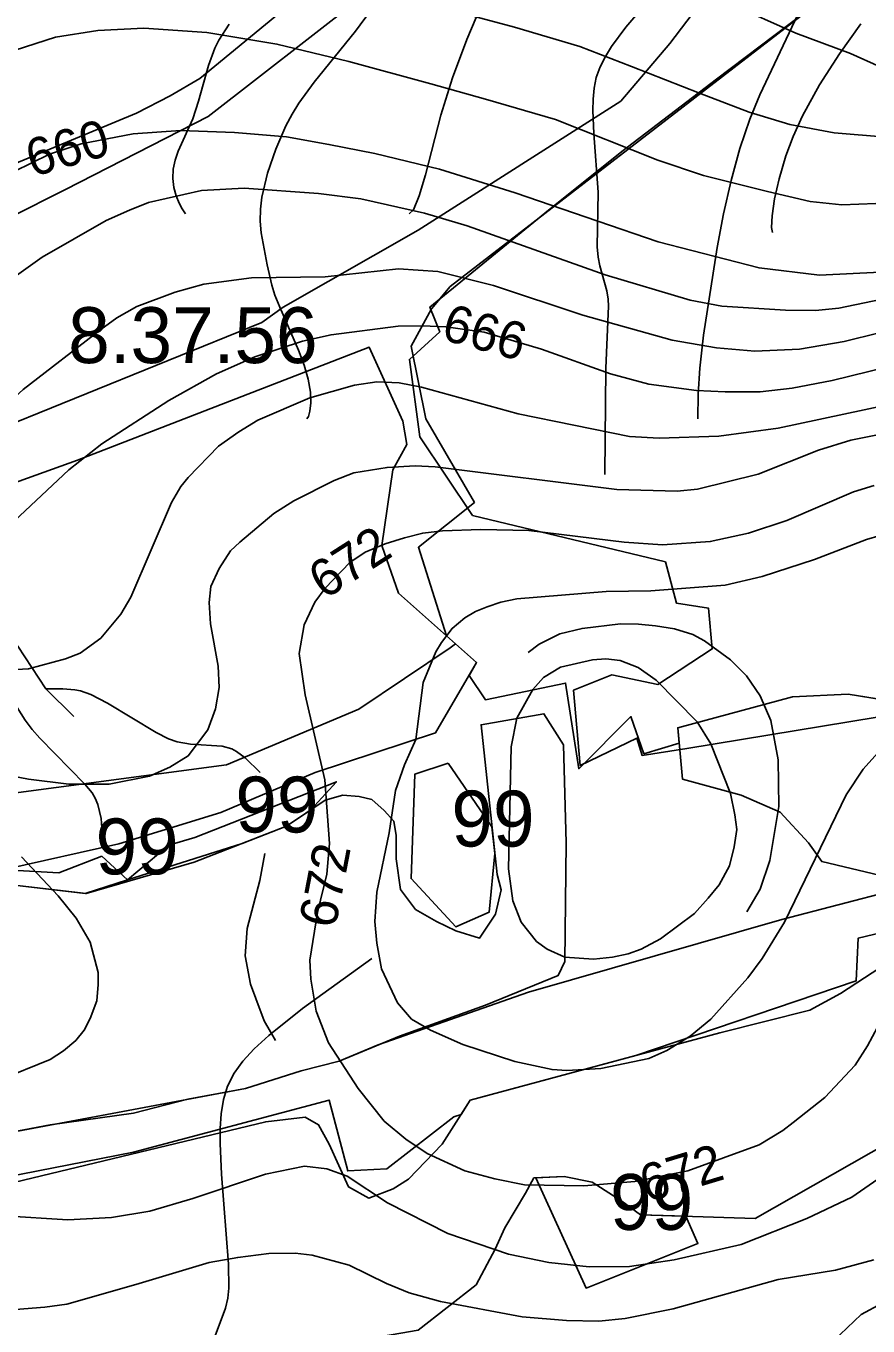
# Model space of a CAD drawing. Extents: x -709584 to -702006, y -1161789 to -1157496.
# Drawn here: x -706462.3 to -706236.4, y -1160518.2 to -1160169 of the extents above; entities that cross this region are included whole.
import ezdxf

# ---------------------------------------------------------------- set-up
doc = ezdxf.new("R2010")
doc.units = 0
for name, color, linetype in [('102_obvod PÚ', 7, 'Continuous'), ('120_vrstevnice hlavní', 7, 'Continuous'), ('121_vrstevnice hlavní_popis', 7, 'Continuous'), ('122_vrstevnice základní', 7, 'Continuous'), ('124_vrstevnice doplňková', 7, 'Continuous'), ('408_BPEJ_linie', 7, 'Continuous'), ('409_BPEJ_popis', 7, 'Continuous'), ('411_akumulovaný odtok', 7, 'Continuous'), ('419_LPIS PB', 7, 'Continuous')]:
    doc.layers.add(name, color=color, linetype=linetype)

msp = doc.modelspace()

# ---------------------------------------------------------------- linework, layer by layer
at = {"layer": '102_obvod PÚ'}
for points in [[(-706359.43, -1160258.57), (-706351.29, -1160251.18), (-706353.92, -1160244.52), (-706323.05, -1160219.34), (-706302.42, -1160202.71), (-706277.05, -1160183.32), (-706245.92, -1160159.66)], [(-706245.92, -1160159.66), (-706277.05, -1160183.32), (-706302.42, -1160202.71), (-706323.05, -1160219.34), (-706353.92, -1160244.52), (-706351.29, -1160251.18), (-706359.43, -1160258.57), (-706356.6, -1160279.34), (-706342.48, -1160300.47), (-706290.74, -1160312.96), (-706287.73, -1160324.07), (-706279.13, -1160325.42), (-706278.18, -1160336.32), (-706292.79, -1160345.84), (-706305.11, -1160343.25), (-706315.41, -1160347.43), (-706313.62, -1160367.6), (-706298.39, -1160360.29), (-706297.01, -1160364.93), (-706285.01, -1160363.05), (-706219.24, -1160352.25)], [(-706219.24, -1160352.25), (-706285.01, -1160363.05), (-706297.01, -1160364.93), (-706298.39, -1160360.29), (-706313.62, -1160367.6), (-706315.41, -1160347.43), (-706305.11, -1160343.25), (-706292.79, -1160345.84), (-706278.18, -1160336.32), (-706279.13, -1160325.42), (-706287.73, -1160324.07), (-706290.74, -1160312.96), (-706342.48, -1160300.47), (-706356.6, -1160279.34), (-706359.43, -1160258.57)]]:
    msp.add_lwpolyline(points, dxfattribs=at)
at = {"layer": '120_vrstevnice hlavní'}
for points in [[(-706406.41, -1160197.67), (-706420.89, -1160197.05), (-706433.54, -1160198.03), (-706447.53, -1160200.69), (-706456.05, -1160203.43), (-706465.53, -1160208.15), (-706473.52, -1160213.84), (-706491, -1160227.07), (-706512.32, -1160245.59)], [(-706233.09, -1160235.12), (-706249.34, -1160235.97), (-706265.58, -1160233.98), (-706292.65, -1160226.99), (-706308.9, -1160221.44), (-706331.07, -1160213.8), (-706351.38, -1160207.47), (-706368.68, -1160203.29), (-706381.04, -1160200.81), (-706392.42, -1160198.81), (-706406.41, -1160197.67)], [(-706233.38, -1160278.72), (-706240.95, -1160280.28), (-706249.62, -1160282.99), (-706265.87, -1160289.41), (-706282.11, -1160293.4), (-706287.53, -1160293.97), (-706303.77, -1160293.54), (-706352.5, -1160287.41), (-706357.92, -1160287.13), (-706365.44, -1160287.56), (-706374.36, -1160289.06), (-706379.58, -1160291.12), (-706390.41, -1160296.53), (-706395.82, -1160299.95), (-706404.94, -1160307.65), (-706407.45, -1160310), (-706410.5, -1160314.77), (-706412.75, -1160319.53), (-706413.2, -1160323.89), (-706412.78, -1160329.59), (-706410.78, -1160340.99), (-706410.5, -1160346.69), (-706411.5, -1160352.39), (-706413.49, -1160358.09), (-706418.76, -1160365.07), (-706423.75, -1160368.06), (-706429.16, -1160370.49), (-706439.99, -1160372.62), (-706450.82, -1160372.62), (-706461.65, -1160371.34), (-706488.73, -1160366.07)], [(-706468.21, -1160488.61), (-706451.11, -1160489.61), (-706439.42, -1160489.07), (-706429.08, -1160487.31), (-706417.57, -1160483.93), (-706398.06, -1160477.41), (-706387.56, -1160475.22), (-706381.57, -1160475.93), (-706376.16, -1160477.93), (-706365.33, -1160485.05), (-706349.08, -1160493.31), (-706332.84, -1160498.87), (-706322.01, -1160501.15), (-706311.18, -1160502.29), (-706300.35, -1160502.15), (-706288.38, -1160500.44), (-706270.43, -1160496.31), (-706252.76, -1160489.32), (-706240.72, -1160483.55), (-706232.52, -1160477.93)]]:
    msp.add_lwpolyline(points, dxfattribs=at)
at = {"layer": '122_vrstevnice základní'}
for points in [[(-706368.04, -1160159.39), (-706331.2, -1160169.31), (-706313.68, -1160174.53), (-706299.81, -1160179.91), (-706281.61, -1160187.09), (-706268.21, -1160192.2), (-706257.3, -1160195.52), (-706245.42, -1160197.68), (-706231.38, -1160198.92), (-706207.73, -1160200.35), (-706180.37, -1160203.34), (-706173.8, -1160204.42), (-706166.69, -1160206.48), (-706160.48, -1160208.44), (-706153.01, -1160211.61), (-706147.31, -1160214.96), (-706141.61, -1160219.16), (-706112.68, -1160245.09), (-706085.18, -1160267.6), (-706069.22, -1160278.01), (-706048.7, -1160288.55), (-706037.31, -1160295.82), (-706023.91, -1160306.79)], [(-706273.31, -1160163.12), (-706255.75, -1160170.97), (-706241.07, -1160176.41), (-706233.09, -1160179.97), (-706223.12, -1160183.53), (-706201.17, -1160188.52), (-706187.21, -1160190.37), (-706173.24, -1160192.94), (-706161.28, -1160197.07), (-706149.31, -1160202.2), (-706139.33, -1160207.47), (-706125.22, -1160217.59), (-706114.25, -1160227.28), (-706091.31, -1160251.07), (-706082.33, -1160258.06), (-706072.36, -1160264.33), (-706060.53, -1160270.31), (-706052.12, -1160273.87), (-706033.99, -1160279.91), (-705988.29, -1160297.96)], [(-706375.67, -1160178.57), (-706394.98, -1160173.87), (-706413.78, -1160170.81), (-706430.72, -1160169.63), (-706443.05, -1160170.28), (-706454.38, -1160172.06), (-706465.2, -1160175.48), (-706475.34, -1160180.88), (-706483.65, -1160187.72), (-706491.11, -1160195.88), (-706502.82, -1160210.9), (-706514.66, -1160223.29), (-706532.55, -1160239.97), (-706558.13, -1160260.92)], [(-706220.55, -1160216.16), (-706243.35, -1160217.02), (-706251.9, -1160216.16), (-706263.3, -1160213.46), (-706280.53, -1160209.15), (-706292.76, -1160205.03), (-706320.21, -1160194.17), (-706339.04, -1160188.65), (-706353.71, -1160184.55), (-706375.67, -1160178.57)], [(-706221.41, -1160240.1), (-706244.21, -1160244.8), (-706250.46, -1160245.42), (-706258.46, -1160245.38), (-706275.56, -1160244.24), (-706284.1, -1160242.67), (-706306.9, -1160235.83), (-706343.95, -1160222.72), (-706355.35, -1160219.3), (-706372.45, -1160215.45), (-706383.85, -1160214.03), (-706403.8, -1160212.6), (-706415.2, -1160213.17), (-706429.45, -1160216.45), (-706434.55, -1160218.47), (-706440.85, -1160221.29), (-706457.95, -1160231.13), (-706472.2, -1160241.24)], [(-706223.97, -1160249.08), (-706242.78, -1160253.78), (-706254.75, -1160255.78), (-706266.72, -1160256.35), (-706276.98, -1160255.49), (-706288.95, -1160253.36), (-706312.89, -1160246.66), (-706336.83, -1160238.68), (-706351.79, -1160234.97), (-706362.33, -1160234.24), (-706382.05, -1160236.4)], [(-706382.05, -1160236.4), (-706401.81, -1160236.68), (-706414.63, -1160238.39), (-706422.32, -1160240.53), (-706432.58, -1160244.38), (-706437.92, -1160247.43), (-706442.27, -1160250.51), (-706463.08, -1160266.61), (-706476.9, -1160279.29), (-706488.87, -1160287.98)], [(-706466.92, -1160303.37), (-706450.82, -1160288.27), (-706441.99, -1160281.28), (-706424.03, -1160269.6), (-706411.21, -1160262.48), (-706400.95, -1160257.92), (-706388.13, -1160253.64), (-706380.43, -1160251.93), (-706362.48, -1160249.65), (-706355.95, -1160249.56), (-706349.65, -1160249.79), (-706339.39, -1160251.22), (-706324, -1160255.78), (-706305.48, -1160262.48), (-706295.22, -1160265.18), (-706282.4, -1160266.89), (-706274.7, -1160267.32), (-706265.26, -1160267.25), (-706256.75, -1160266.32), (-706245.94, -1160264.23), (-706220.84, -1160258.06)], [(-706219.76, -1160268.37), (-706260.45, -1160277.01), (-706276.41, -1160279.15), (-706292.37, -1160279.72), (-706300.35, -1160279.29), (-706330.27, -1160273.16), (-706356.21, -1160266.04), (-706362.19, -1160264.9), (-706368.18, -1160264.61), (-706374.16, -1160265.47), (-706386.13, -1160268.89), (-706400.09, -1160274.87), (-706405.25, -1160278.03), (-706410.66, -1160281.85)], [(-706410.66, -1160281.85), (-706418.76, -1160290.26), (-706420.77, -1160292.7), (-706423.32, -1160296.96), (-706434.15, -1160322.47), (-706436.86, -1160327.03), (-706442.27, -1160333.44), (-706447.83, -1160337.43), (-706451.68, -1160338.99), (-706461.65, -1160341.7), (-706505.54, -1160344.12)], [(-706234.74, -1160292.45), (-706240.22, -1160294.11), (-706258.17, -1160301.8), (-706268.43, -1160305.22), (-706278.69, -1160307.5), (-706291.51, -1160308.36), (-706301.77, -1160307.65), (-706327.42, -1160304.51), (-706340.25, -1160304.23), (-706350.51, -1160304.65), (-706355.87, -1160305.23), (-706360.77, -1160306.51), (-706365.9, -1160308.07)], [(-706365.9, -1160308.07), (-706371.26, -1160310.38), (-706375.44, -1160313.09), (-706382, -1160320.04), (-706384.83, -1160323.79), (-706387.7, -1160329.88), (-706388.98, -1160337.57), (-706387.41, -1160348.68), (-706382.14, -1160371.48), (-706380.86, -1160388.58), (-706381.57, -1160396.85), (-706384.14, -1160407.11), (-706386.13, -1160419.93), (-706385.85, -1160425.06), (-706384.42, -1160433.61), (-706381.14, -1160442.16), (-706373.16, -1160454.42), (-706366.18, -1160463.11), (-706360.43, -1160468), (-706354.64, -1160471.8), (-706344.52, -1160476.5), (-706336.51, -1160478.66), (-706328.56, -1160480.21), (-706312.6, -1160480.49), (-706298.92, -1160479.35), (-706284.68, -1160476.5), (-706265.58, -1160469.52), (-706259.21, -1160465.62), (-706256.46, -1160463.53), (-706247.91, -1160456.84), (-706239.79, -1160448.15), (-706236.47, -1160442.92), (-706233.8, -1160437.89)], [(-706233.06, -1160305.86), (-706236.8, -1160306.93), (-706250.76, -1160312.35), (-706264.73, -1160316.91), (-706274.7, -1160319.19), (-706294.65, -1160320.76), (-706306.62, -1160320.9), (-706330.56, -1160322.89), (-706334.94, -1160323.79), (-706338.54, -1160325.03), (-706341.65, -1160326.3), (-706344.52, -1160328.02), (-706347.98, -1160330.81), (-706350.79, -1160334.58)], [(-706350.79, -1160334.58), (-706352.36, -1160337.14), (-706355.71, -1160345.33), (-706357.67, -1160360.66), (-706360.78, -1160367.43), (-706363.19, -1160374.33), (-706364.9, -1160385.73), (-706368.18, -1160401.69), (-706368.72, -1160409.57), (-706368.18, -1160415.37), (-706366.89, -1160422.21), (-706362.62, -1160431.33), (-706358.91, -1160435.75), (-706353.78, -1160438.74), (-706345.09, -1160442.59), (-706331.13, -1160447.15), (-706321.15, -1160449.28), (-706317.16, -1160449.57), (-706308.04, -1160449), (-706295.22, -1160446.29), (-706290.37, -1160444.16), (-706284.1, -1160440.31), (-706278.55, -1160435.75), (-706268.57, -1160424.63), (-706264.73, -1160419.5), (-706258.74, -1160409.67), (-706242.21, -1160375.47), (-706237.65, -1160368.63), (-706231.38, -1160361.65)], [(-706298.08, -1160341.35), (-706293.22, -1160344.69), (-706282.24, -1160355.89), (-706278.55, -1160361.79), (-706273.28, -1160375.19), (-706272.14, -1160380.89), (-706271.58, -1160384.86), (-706272.28, -1160389.44), (-706273.56, -1160394.57), (-706276.27, -1160399.7), (-706279.27, -1160403.3), (-706282.96, -1160407.39), (-706292.08, -1160414.23), (-706297.21, -1160416.94), (-706300.72, -1160418.22), (-706304.91, -1160419.08), (-706310.04, -1160419.65), (-706317.73, -1160419.08), (-706322.44, -1160416.94), (-706325.29, -1160414.94), (-706329.42, -1160409.67), (-706331.7, -1160403.97), (-706332.84, -1160395.42), (-706332.12, -1160362.65), (-706330.56, -1160354.95), (-706326.28, -1160347.26), (-706323.42, -1160343.99), (-706318.87, -1160341.27), (-706310.32, -1160339.28), (-706306.74, -1160338.97), (-706302.91, -1160339.42), (-706298.08, -1160341.35)], [(-706471.91, -1160514.26), (-706457.25, -1160513.14), (-706451.39, -1160512.27), (-706432.87, -1160507), (-706413.21, -1160501.15), (-706405.51, -1160499.73), (-706397.15, -1160498.72), (-706390.12, -1160498.59), (-706385.56, -1160499.16), (-706375.59, -1160501.86), (-706365.61, -1160506.71), (-706359.53, -1160509.25), (-706351.08, -1160511.55), (-706329.13, -1160515.69), (-706317.31, -1160516.66)], [(-706317.31, -1160516.66), (-706308.61, -1160516.83), (-706301.49, -1160516.11), (-706288.67, -1160513.55), (-706260.45, -1160505.71), (-706245.06, -1160503.15), (-706234.8, -1160500.44)]]:
    msp.add_lwpolyline(points, dxfattribs=at)
at = {"layer": '124_vrstevnice doplňková'}
for points in [[(-706268.86, -1160406.96), (-706265.3, -1160400.84), (-706262.73, -1160393.14), (-706260.31, -1160378.61), (-706260.45, -1160366.07), (-706262.45, -1160355.52), (-706265.29, -1160348.95), (-706269, -1160343.55), (-706273.28, -1160339.28), (-706280.26, -1160334.15), (-706283.34, -1160332.44), (-706288.26, -1160330.94), (-706293.37, -1160330.16), (-706297.96, -1160329.68), (-706302.74, -1160329.56), (-706313.08, -1160330.81), (-706319.02, -1160332.3), (-706324.57, -1160335.01), (-706327.57, -1160337.28)], [(-706463.5, -1160392.14), (-706453.65, -1160402.67), (-706448.83, -1160408.67), (-706445.12, -1160415.09), (-706442.98, -1160423.25), (-706442.98, -1160426.49), (-706443.31, -1160430.88), (-706445.12, -1160435.61), (-706446.69, -1160438.74), (-706448.97, -1160441.45), (-706452.23, -1160444.29), (-706455.81, -1160446.58), (-706469.63, -1160452.14)], [(-706395.38, -1160441.51), (-706398.39, -1160436.18), (-706400.67, -1160430.19), (-706402.06, -1160426.37), (-706403.52, -1160418.79), (-706402.95, -1160411.38), (-706399.53, -1160398.56), (-706398.24, -1160391.29)]]:
    msp.add_lwpolyline(points, dxfattribs=at)
at = {"layer": '408_BPEJ_linie'}
for points in [[(-706250, -1160163), (-706348.5, -1160239), (-706353.5, -1160245), (-706359, -1160255), (-706355, -1160274.5), (-706342, -1160297), (-706357, -1160309), (-706349.51, -1160332.79), (-706347.02, -1160335)], [(-706103, -1160268), (-706099, -1160299.5), (-706150, -1160307.5), (-706155.5, -1160318), (-706160.17, -1160320.67), (-706164.3, -1160322.1), (-706167.91, -1160324.42), (-706191, -1160329.5), (-706202.5, -1160346.5), (-706228.47, -1160350.62), (-706241.64, -1160348.48), (-706256.65, -1160349.23), (-706287.44, -1160357.51), (-706287.04, -1160361.64), (-706296.5, -1160364.5), (-706300, -1160354.5), (-706314, -1160368.5), (-706317.5, -1160345.5), (-706339, -1160350), (-706343.43, -1160343.48), (-706341.4, -1160340), (-706347.02, -1160335)], [(-706487.5, -1160470.1), (-706455.81, -1160464.16), (-706433.5, -1160461), (-706418.93, -1160457.25), (-706403.41, -1160454.34), (-706388.5, -1160449.6), (-706378.3, -1160447), (-706367.83, -1160442.67), (-706327.5, -1160428.5), (-706259.5, -1160409), (-706138.5, -1160377.5), (-706087, -1160370.5), (-706076.46, -1160369.43), (-706061.5, -1160368.4), (-706058.29, -1160367.58), (-705974, -1160359), (-705934, -1160351), (-705922, -1160347), (-705893.5, -1160331), (-705797.5, -1160292), (-705762, -1160283.5), (-705718.5, -1160279)], [(-706640, -1160329), (-706623.5, -1160345), (-706555, -1160369.5), (-706507.5, -1160377), (-706476.5, -1160376.5), (-706408.5, -1160367.5), (-706373, -1160352.5), (-706348.5, -1160336), (-706347.02, -1160335)], [(-706349, -1160367), (-706358, -1160370), (-706359, -1160398), (-706347, -1160411), (-706338, -1160407), (-706336.5, -1160391.28), (-706337.27, -1160384.15), (-706349, -1160367)], [(-706404.32, -1160388.56), (-706392.4, -1160383.9), (-706385.89, -1160379.52), (-706379, -1160372), (-706417, -1160387), (-706424, -1160389), (-706435.11, -1160398.37)], [(-706435.11, -1160398.37), (-706404.32, -1160388.56)], [(-706442, -1160392), (-706453.5, -1160396.5), (-706467.75, -1160395.62), (-706469.3, -1160399.3), (-706446.42, -1160401.97), (-706435.11, -1160398.37)], [(-706435.11, -1160398.37), (-706442, -1160392)], [(-706209.45, -1160406.95), (-706239, -1160414), (-706239.5, -1160425.5), (-706298.67, -1160445.5), (-706343.1, -1160457.5), (-706345.54, -1160461.34), (-706347.5, -1160462), (-706365.5, -1160476), (-706376, -1160476.5), (-706381, -1160457.5), (-706433.5, -1160471.5), (-706502.5, -1160485)], [(-706285.28, -1160488.71), (-706297.4, -1160488.3), (-706302.4, -1160484.6), (-706310.4, -1160479.5), (-706317.9, -1160478), (-706325.47, -1160478.37), (-706312, -1160508), (-706282, -1160496), (-706285.28, -1160488.71)]]:
    msp.add_lwpolyline(points, dxfattribs=at)
at = {"layer": '411_akumulovaný odtok'}
msp.add_line((-706449.49, -1160354.5), (-706456.99, -1160347), dxfattribs=at)
for points in [[(-706281.99, -1160274.5), (-706281.94, -1160267.95), (-706281.49, -1160260.88), (-706280.54, -1160252.08), (-706276.8, -1160228.54), (-706275.1, -1160219.5), (-706273.09, -1160210.53), (-706270.75, -1160201.93), (-706268.09, -1160194.02), (-706265.38, -1160187.53), (-706239.52, -1160132.7)], [(-706306.99, -1160289.5), (-706306.71, -1160260.89), (-706306.01, -1160244.25), (-706306.1, -1160242.37), (-706306.47, -1160240.15), (-706308.33, -1160233.41), (-706308.8, -1160231.07), (-706309.04, -1160228.35), (-706308.77, -1160213.64), (-706309.94, -1160197.94), (-706310.23, -1160191.74), (-706310.16, -1160188.7), (-706309.87, -1160185.73), (-706309.27, -1160182.86), (-706308.22, -1160180), (-706306.83, -1160177.25), (-706305.17, -1160174.57), (-706301.33, -1160169.38), (-706297.07, -1160164.32), (-706292.2, -1160158.88), (-706271.99, -1160137)], [(-706359.49, -1160219.5), (-706358.35, -1160218.39), (-706356.77, -1160214.67), (-706355.13, -1160208.96), (-706351.03, -1160192.95), (-706347.87, -1160182.99), (-706344.04, -1160172.67), (-706339.26, -1160161.35)], [(-706386.99, -1160274.5), (-706386.52, -1160273.94), (-706386.11, -1160272.45), (-706385.87, -1160270.21), (-706385.95, -1160267.37), (-706386.56, -1160263.89), (-706387.67, -1160260.08), (-706389.15, -1160256.09), (-706394.22, -1160244.56), (-706395.52, -1160241.3), (-706396.37, -1160238.61), (-706397.64, -1160233.13), (-706399.17, -1160224.54), (-706399.49, -1160221.41), (-706399.41, -1160218.24), (-706399.01, -1160215.03), (-706397.49, -1160208.56), (-706395.31, -1160202.1), (-706392.55, -1160195.8), (-706390.92, -1160192.75), (-706389.07, -1160189.78), (-706384.95, -1160184.07), (-706373.88, -1160170.39), (-706369.83, -1160164.94)], [(-706419.49, -1160219.5), (-706420.45, -1160218.12), (-706421.24, -1160216.6), (-706422.02, -1160214.66), (-706422.64, -1160212.42), (-706422.95, -1160209.98), (-706422.82, -1160207.52), (-706422.29, -1160205.04), (-706421.48, -1160202.62), (-706417.57, -1160193.96), (-706416.05, -1160189.26), (-706413.31, -1160179.65), (-706411.61, -1160175.01), (-706410.55, -1160172.8), (-706407.79, -1160168.51)], [(-706261.99, -1160224.5), (-706262.27, -1160223.18), (-706262.11, -1160220.04), (-706261.42, -1160215.43), (-706260.19, -1160210.05), (-706258.4, -1160203.92), (-706256.44, -1160198.67), (-706253.95, -1160193.19), (-706249.35, -1160184.85), (-706243.98, -1160176.53), (-706238.25, -1160168.41)], [(-706456.99, -1160347), (-706464.55, -1160335.57), (-706467.18, -1160332.19), (-706470.55, -1160329.57), (-706481.99, -1160322)], [(-706441.99, -1160389.5), (-706441.91, -1160385.59), (-706442.17, -1160381.88), (-706443.01, -1160378.09), (-706443.73, -1160376.41), (-706444.59, -1160374.97), (-706446.53, -1160372.61), (-706458.59, -1160360.3), (-706460.66, -1160357.96), (-706462.58, -1160355.46), (-706466.84, -1160348.65), (-706481.99, -1160322)], [(-706399.49, -1160369.5), (-706403.48, -1160365.6), (-706405.86, -1160363.85), (-706407.11, -1160363.17), (-706409.64, -1160362.42), (-706418.2, -1160361.9), (-706421.79, -1160361.32), (-706424.09, -1160360.47), (-706427.43, -1160358.77), (-706440.47, -1160350.92), (-706444.89, -1160348.53), (-706447.67, -1160347.6), (-706449.24, -1160347.3), (-706452.41, -1160347.01), (-706456.99, -1160347)], [(-706369.49, -1160419.5), (-706388.08, -1160432.87), (-706397.2, -1160440.15), (-706401.09, -1160443.7), (-706404.15, -1160447.02), (-706406.48, -1160450.27), (-706408.26, -1160453.77), (-706409.34, -1160457.37), (-706409.94, -1160461.18), (-706410.21, -1160465.13), (-706410.24, -1160469.18), (-706409.87, -1160477.43), (-706408.01, -1160501.57), (-706407.86, -1160508.01), (-706408.12, -1160510.69), (-706408.82, -1160513.39), (-706411.83, -1160521.55)]]:
    msp.add_lwpolyline(points, dxfattribs=at)
at = {"layer": '419_LPIS PB'}
for points in [[(-706481.73, -1160227.97), (-706451.7, -1160212.91), (-706413.42, -1160193.32), (-706372.87, -1160161.69), (-706316.57, -1160111.98), (-706297.8, -1160096.91), (-706288.79, -1160092.4), (-706282.03, -1160091.64), (-706276.03, -1160097.67), (-706273.02, -1160113.48), (-706272.27, -1160140.6), (-706273.02, -1160151.9), (-706289.54, -1160173.74), (-706302.7, -1160189.21), (-706357.04, -1160223.9), (-706393.27, -1160244.55), (-706399.04, -1160248.68), (-706474.5, -1160279.3)], [(-706394, -1160165.3), (-706415.7, -1160183.1), (-706423.64, -1160187.76), (-706432.66, -1160192.44), (-706515.71, -1160226.9)], [(-706487.9, -1160299.8), (-706448.5, -1160285.6), (-706370.22, -1160255.29), (-706361.22, -1160275.14), (-706360.11, -1160281.45), (-706363.86, -1160288.22), (-706366.87, -1160308.56), (-706362.36, -1160321.36), (-706341.4, -1160340), (-706352.4, -1160358.9), (-706384.7, -1160369.5), (-706410, -1160380.3), (-706437.4, -1160388.7), (-706467.7, -1160395.5)], [(-706231.1, -1160397.6), (-706248.76, -1160393.46), (-706252.37, -1160388.4), (-706259.93, -1160380.19), (-706270.39, -1160375.59), (-706286.1, -1160371.3), (-706287.44, -1160357.51), (-706256.65, -1160349.23), (-706241.64, -1160348.48), (-706213.86, -1160352.99)], [(-706469.3, -1160399.3), (-706446.2, -1160402), (-706417.2, -1160393.6), (-706392.4, -1160383.9), (-706382, -1160376.9), (-706377.3, -1160375.6), (-706372.9, -1160376), (-706369.5, -1160376.8), (-706366.2, -1160379.7), (-706363.6, -1160382.6), (-706363, -1160386.4), (-706363, -1160392.7), (-706361.8, -1160400.9), (-706357.8, -1160406.3), (-706352.2, -1160409.5), (-706347, -1160412), (-706340.6, -1160414), (-706336.3, -1160407.6), (-706334.8, -1160401), (-706335.9, -1160396.9), (-706340.2, -1160356.7), (-706323.32, -1160353.75), (-706318.07, -1160362.04), (-706317.32, -1160388.4), (-706317.7, -1160420.3), (-706319.5, -1160424), (-706339, -1160432), (-706362.1, -1160440.3), (-706378.3, -1160447), (-706388.5, -1160449.6), (-706403.41, -1160454.34), (-706487.5, -1160470.1)], [(-706501.7, -1160488.3), (-706397.98, -1160463.3), (-706387.4, -1160462.1), (-706383.8, -1160464.1), (-706381, -1160469.3), (-706375.8, -1160480.8), (-706370.3, -1160483.8), (-706363.8, -1160481.3), (-706359.7, -1160478.7), (-706350.6, -1160469.3), (-706343.1, -1160457.5), (-706276.1, -1160439.4), (-706252, -1160433.36), (-706243.74, -1160428.84), (-706222.4, -1160414.9)], [(-706020.91, -1160436.41), (-706153.97, -1160452.52), (-706186.9, -1160459.1), (-706197.2, -1160455.2), (-706219.3, -1160461.5), (-706230.3, -1160468.6), (-706266.65, -1160489.33), (-706297.4, -1160488.3), (-706302.4, -1160484.6), (-706310.4, -1160479.5), (-706317.9, -1160478), (-706326, -1160478.4), (-706328.3, -1160482.5), (-706333.8, -1160491.8), (-706336.4, -1160497.5), (-706341.5, -1160507.1), (-706357.09, -1160519.25), (-706470, -1160538.8)], [(-706491.69, -1160555.72), (-706403.1, -1160535.38), (-706356.1, -1160526.34), (-706314.05, -1160522.58), (-706292.28, -1160521.82), (-706283.27, -1160523.33), (-706275.76, -1160526.34), (-706273.51, -1160530.86), (-706272.01, -1160534.63), (-706269.01, -1160538.4), (-706266, -1160538.4), (-706260, -1160535.38), (-706253.24, -1160529.36), (-706238.23, -1160515.05), (-706226.96, -1160509.02), (-706207.45, -1160499.23), (-706188.68, -1160481.38), (-706174.41, -1160471.59), (-706149.64, -1160464.05), (-706131.62, -1160462.55), (-706117.3, -1160463.9), (-706096.3, -1160462.9), (-706046.78, -1160451.25), (-705983.9, -1160440)]]:
    msp.add_lwpolyline(points, dxfattribs=at)

# ---------------------------------------------------------------- texts
at = {"layer": '121_vrstevnice hlavní_popis'}
for s, rotation, p in [('660', 16.1431, (-706460.58, -1160209.64)), ('666', 344.5986, (-706351.22, -1160253.1)), ('672', 32.5901, (-706382.23, -1160323.21)), ('672', 79.1007, (-706379.33, -1160411.65)), ('672', 16.8169, (-706295.72, -1160485.06))]:
    msp.add_text(s, height=10, rotation=rotation, dxfattribs=at).set_placement(p)
at = {"layer": '409_BPEJ_popis'}
for s, p in [('8.37.56', (-706451, -1160259.56)), ('99', (-706406.14, -1160385.62)), ('99', (-706348.16, -1160389.39)), ('99', (-706443.66, -1160396.87)), ('99', (-706305.59, -1160492.35))]:
    msp.add_text(s, height=15, dxfattribs=at).set_placement(p)

doc.saveas('drawing.dxf')
